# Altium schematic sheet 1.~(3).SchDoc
size 420 x 297 mm
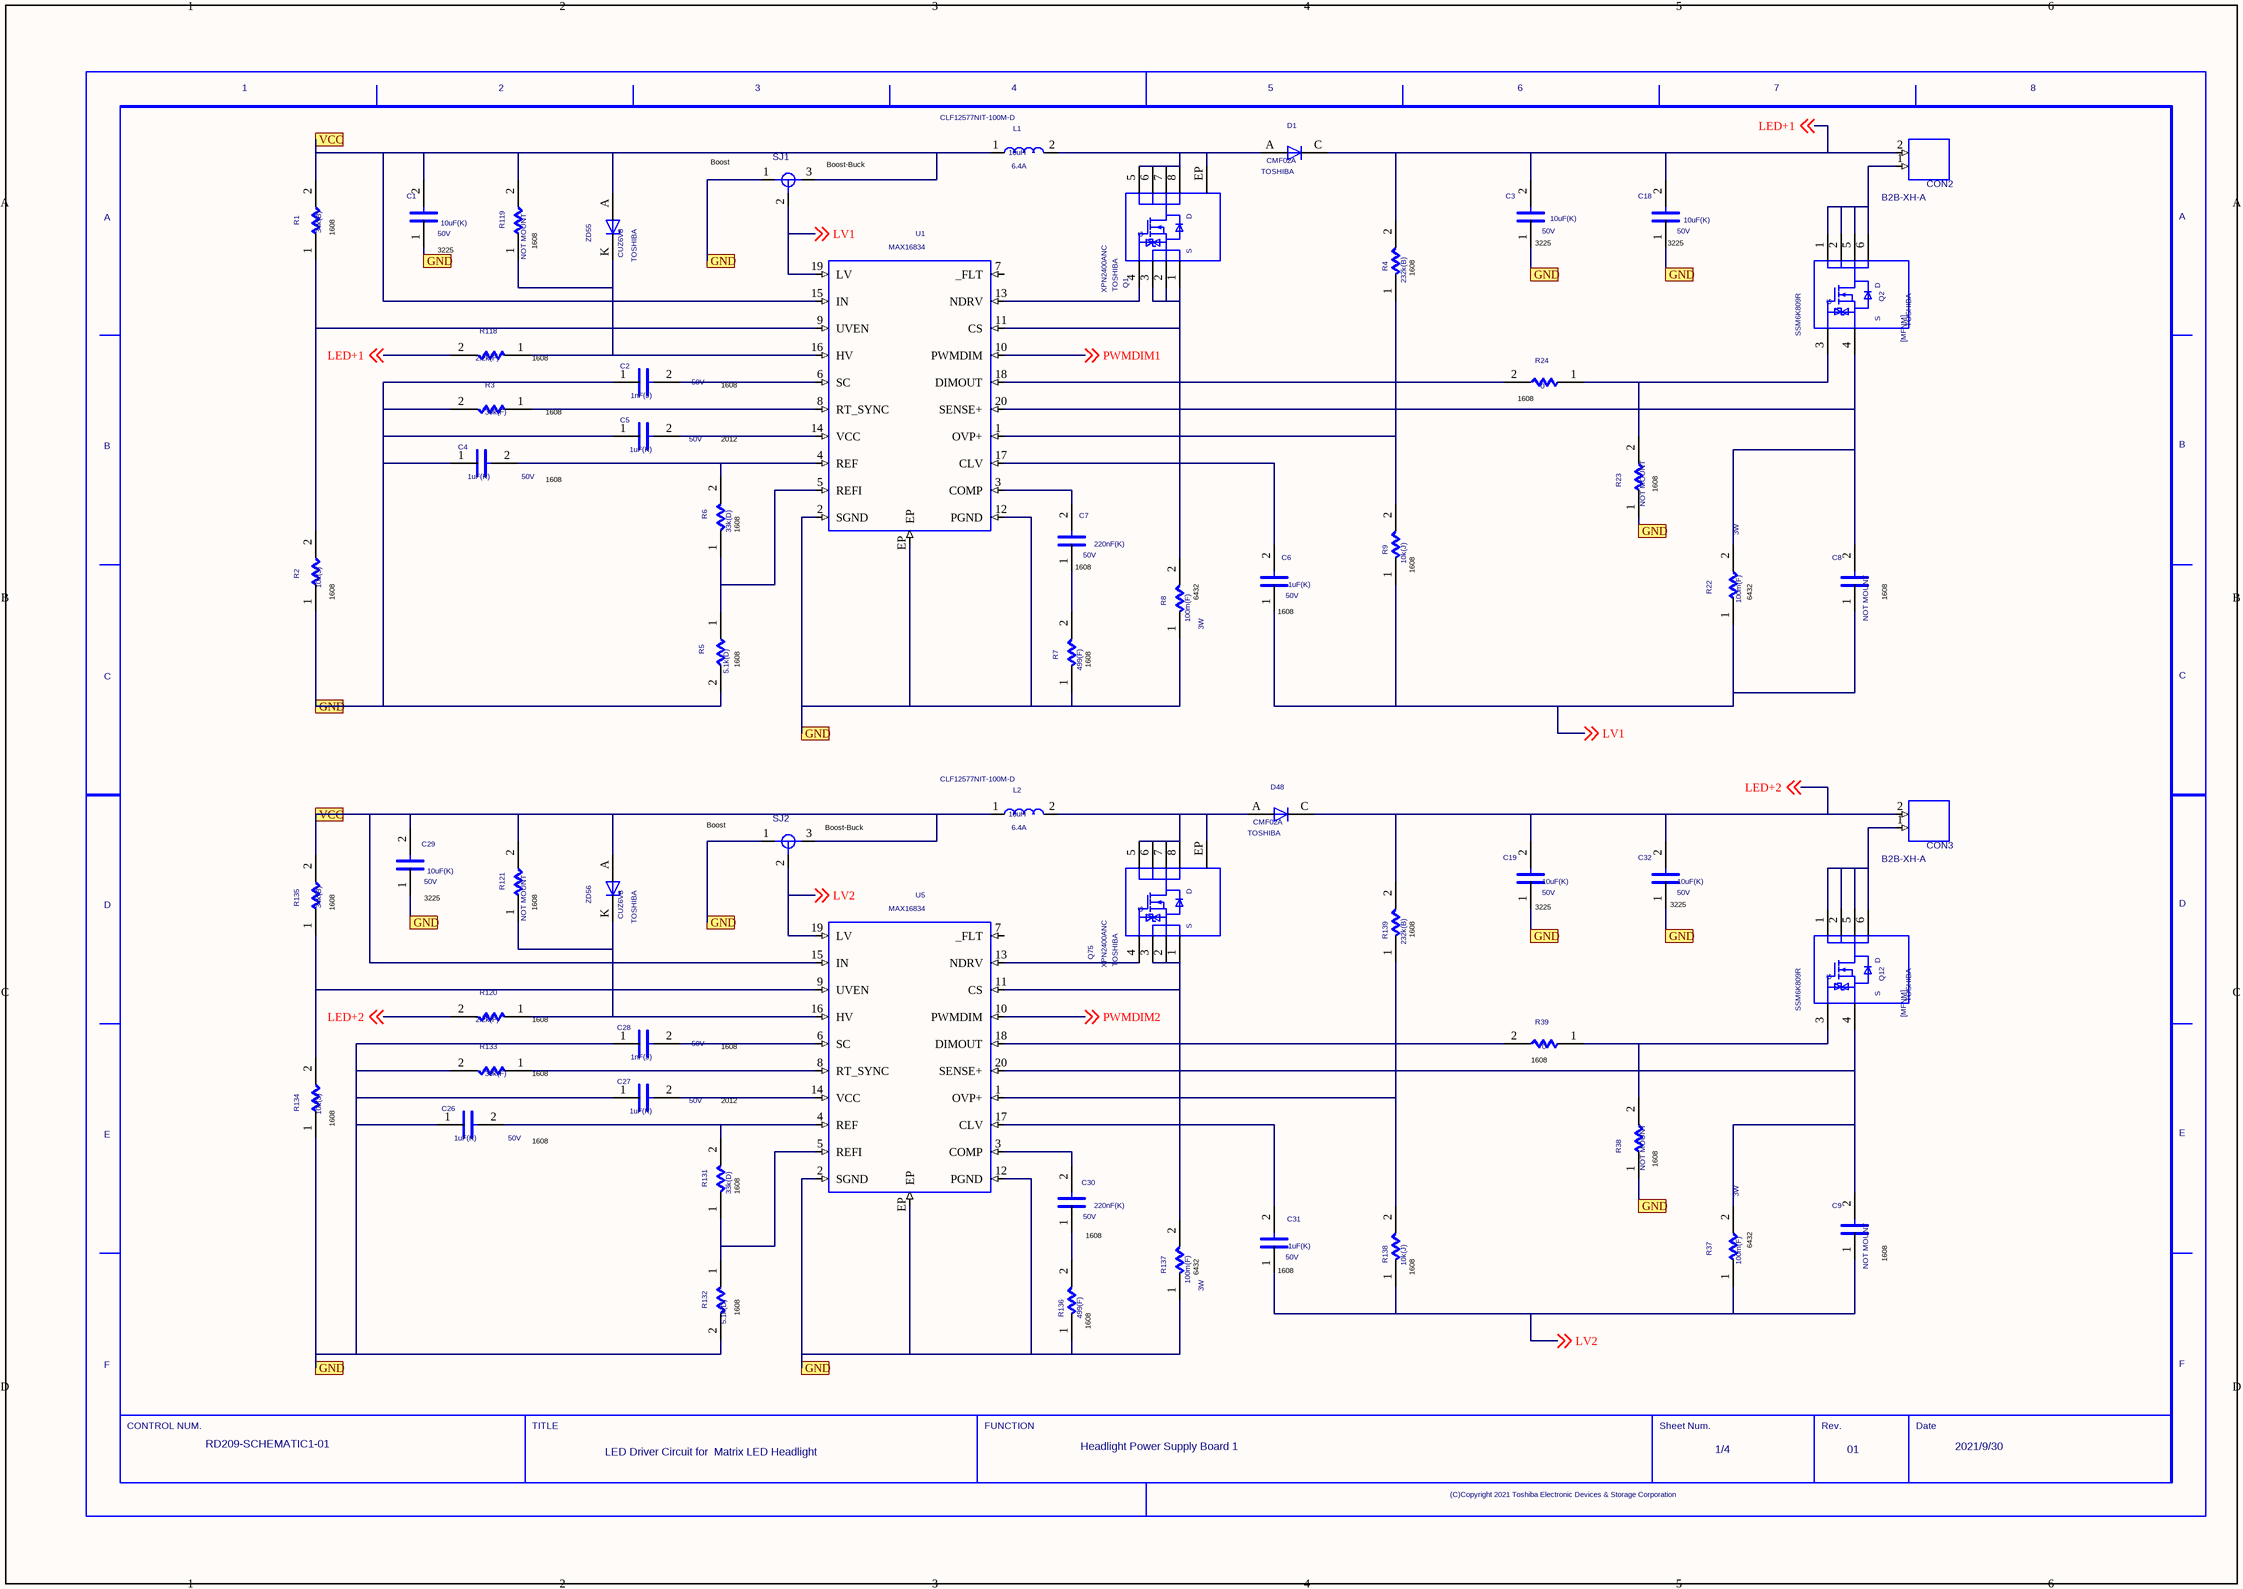
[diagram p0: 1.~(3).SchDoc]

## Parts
C1  VAL2: 50V  VAL1: 10uF(K)  (hidden comment: C)
C2  VAL2: 50V  VAL1: 1nF(J)  (hidden comment: C)
C3  VAL2: 50V  VAL1: 10uF(K)  (hidden comment: C)
C4  VAL2: 50V  VAL1: 1uF(K)  (hidden comment: C)
C5  VAL2: 50V  VAL1: 1uF(K)  (hidden comment: C)
C6  VAL2: 50V  VAL1: 1uF(K)  (hidden comment: C)
C7  VAL2: 50V  VAL1: 220nF(K)  (hidden comment: C)
C8  NOTMOUNT: NOT MOUNT  (hidden comment: C)
C9  NOTMOUNT: NOT MOUNT  (hidden comment: C)
C18  VAL2: 50V  VAL1: 10uF(K)  (hidden comment: C)
C19  VAL2: 50V  VAL1: 10uF(K)  (hidden comment: C)
C26  VAL2: 50V  VAL1: 1uF(K)  (hidden comment: C)
C27  VAL2: 50V  VAL1: 1uF(K)  (hidden comment: C)
C28  VAL2: 50V  VAL1: 1nF(J)  (hidden comment: C)
C29  VAL2: 50V  VAL1: 10uF(K)  (hidden comment: C)
C30  VAL2: 50V  VAL1: 220nF(K)  (hidden comment: C)
C31  VAL2: 50V  VAL1: 1uF(K)  (hidden comment: C)
C32  VAL2: 50V  VAL1: 10uF(K)  (hidden comment: C)
CON2  B2B-XH-A  [B2B-XH-A]
CON3  B2B-XH-A  [B2B-XH-A]
D1  USERCOMPTEXT3: TOSHIBA  VAL3: CMF02A  (hidden comment: D)
D48  USERCOMPTEXT3: TOSHIBA  VAL3: CMF02A  (hidden comment: D)
L1  VAL3: CLF12577NIT-100M-D  VAL2: 6.4A  VAL1: 10uH  (hidden comment: L)
L2  VAL3: CLF12577NIT-100M-D  VAL2: 6.4A  VAL1: 10uH  (hidden comment: L)
Q1  USERCOMPTEXT3: TOSHIBA  VAL3: XPN2400ANC  (hidden comment: MFNKR1)
Q2  USERCOMPTEXT3: TOSHIBA  VAL3: SSM6K809R  (hidden comment: MFNM)
Q12  USERCOMPTEXT3: TOSHIBA  VAL3: SSM6K809R  (hidden comment: MFNM)
Q75  USERCOMPTEXT3: TOSHIBA  VAL3: XPN2400ANC  (hidden comment: MFNKR1)
R1  VAL1: 34k(B)  (hidden comment: R)
R2  VAL1: 10k(J)  (hidden comment: R)
R3  VAL1: 39k(F)  (hidden comment: R)
R4  VAL1: 232k(B)  (hidden comment: R)
R5  VAL1: 5.1k(D)  (hidden comment: R)
R6  VAL1: 33k(D)  (hidden comment: R)
R7  VAL1: 499(F)  (hidden comment: R)
R8  VAL2: 3W  VAL1: 100m(F)  (hidden comment: R)
R9  VAL1: 10k(J)  (hidden comment: R)
R22  VAL2: 3W  VAL1: 100m(F)  (hidden comment: R)
R23  NOTMOUNT: NOT MOUNT  (hidden comment: R)
R24  VAL1: 0  (hidden comment: R)
R37  VAL2: 3W  VAL1: 100m(F)  (hidden comment: R)
R38  NOTMOUNT: NOT MOUNT  (hidden comment: R)
R39  VAL1: 0  (hidden comment: R)
R118  VAL1: 2.2k(F)  (hidden comment: R)
R119  NOTMOUNT: NOT MOUNT  (hidden comment: R)
R120  VAL1: 2.2k(F)  (hidden comment: R)
R121  NOTMOUNT: NOT MOUNT  (hidden comment: R)
R131  VAL1: 33k(D)  (hidden comment: R)
R132  VAL1: 5.1k(D)  (hidden comment: R)
R133  VAL1: 39k(F)  (hidden comment: R)
R134  VAL1: 10k(J)  (hidden comment: R)
R135  VAL1: 34k(B)  (hidden comment: R)
R136  VAL1: 499(F)  (hidden comment: R)
R137  VAL2: 3W  VAL1: 100m(F)  (hidden comment: R)
R138  VAL1: 10k(J)  (hidden comment: R)
R139  VAL1: 232k(B)  (hidden comment: R)
SJ1  SJ2W  (value not drawn)
SJ2  SJ2W  (value not drawn)
U1  MAX16834
U5  MAX16834
U?  DATE: 2021/9/30  REVISION: 01  SHEETNUMBER: 1/4  FUNCTION: Headlight Power Supply Board 1  TITLE: LED Driver Circuit for / Matrix LED Headlight  DRAWINGNUMBER: RD209-SCHEMATIC1-01  (hidden comment: WAKU_DEF100)
ZD55  USERCOMPTEXT3: TOSHIBA  VAL3: CUZ6V8  (hidden comment: ZD)
ZD56  USERCOMPTEXT3: TOSHIBA  VAL3: CUZ6V8  (hidden comment: ZD)

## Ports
GND, VCC

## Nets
GND: C1.1 C2.1 C3.1 C4.1 C5.1 C18.1 C19.1 C26.1 C27.1 C28.1 C29.1 C32.1 R2.1 R3.2 R5.2 R7.1 R8.1 R23.1 R38.1 R132.2 R133.2 R134.1 R136.1 R137.1 SJ1.1 SJ2.1 U1.2(SGND) U1.12(PGND) U1.EP U5.2(SGND) U5.12(PGND) U5.EP ; port GND
LED+1: C3.2 C18.2 CON2.2 D1.C R4.2 R118.2 ; off-sheet LED+1
LED+2: C19.2 C32.2 CON3.2 D48.C R120.2 R139.2 ; off-sheet LED+2
LED-1: CON2.1 Q2.1 Q2.2 Q2.5 Q2.6
LV1: C6.1 C8.1 R9.1 R22.1 SJ1.2 U1.19(LV) ; off-sheet LV1
LV2: C9.1 C31.1 R37.1 R138.1 SJ2.2 U5.19(LV) ; off-sheet LV2
N00268: R5.1 R6.1 U1.5(REFI)
N00273: R3.1 U1.8(RT_SYNC)
N00275: R1.1 R2.2 U1.9(UVEN)
N00392: D1.A L1.2 Q1.5 Q1.6 Q1.7 Q1.8 Q1.EP
N00398: C7.2 U1.3(COMP)
N00400: C6.2 U1.17(CLV)
N00402: R4.1 R9.2 U1.1(OVP+)
N00897: C8.2 Q2.4 R22.2 U1.20(SENSE+)
N00907: R24.2 U1.18(DIMOUT)
N00925: R118.1 R119.1 U1.16(HV) ZD55.K(C)
N01084: C4.2 R6.2 U1.4(REF)
PWMDIM1: U1.10(PWMDIM) ; off-sheet PWMDIM1
PWMDIM2: U5.10(PWMDIM) ; off-sheet PWMDIM2
SIG2: Q1.1 Q1.2 Q1.3 R8.2 U1.11(CS)
SIG212: C5.2 U1.14(VCC)
SIG213: C2.2 U1.6(SC)
SIG216: Q1.4 U1.13(NDRV)
SIG218: C7.1 R7.2
SIG223: Q2.3 R23.2 R24.1
SIG224: R133.1 U5.8(RT_SYNC)
SIG225: C28.2 U5.6(SC)
SIG229: C26.2 R131.2 U5.4(REF)
SIG230: C31.2 U5.17(CLV)
SIG231: C27.2 U5.14(VCC)
SIG233: R134.2 R135.1 U5.9(UVEN)
SIG235: C30.2 U5.3(COMP)
SIG236: Q75.1 Q75.2 Q75.3 R137.2 U5.11(CS)
SIG237: R138.2 R139.1 U5.1(OVP+)
SIG238: R120.1 R121.1 U5.16(HV) ZD56.K(C)
SIG243: C30.1 R136.2
SIG244: Q12.3 R38.2 R39.1
SIG245: R131.1 R132.1 U5.5(REFI)
SIG250: D48.A L2.2 Q75.5 Q75.6 Q75.7 Q75.8 Q75.EP
SIG251: Q75.4 U5.13(NDRV)
SIG662: R39.2 U5.18(DIMOUT)
SIG663: CON3.1 Q12.1 Q12.2 Q12.5 Q12.6
SIG664: C9.2 Q12.4 R37.2 U5.20(SENSE+)
VCC: C1.2 C29.2 L1.1 L2.1 R1.2 R119.2 R121.2 R135.2 SJ1.3 SJ2.3 U1.15(IN) U5.15(IN) ZD55.A ZD56.A ; port VCC

Not connected (* = marked no-connect by the designer): U1 7(_FLT); U5 7(_FLT)

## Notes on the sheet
- (near SJ1) Boost
- (near SJ1) Boost-Buck
- (near R1) 1608
- (near C1) 3225
- (near R119) 1608
- (near C3) 3225
- (near C18) 3225
- (near R4) 1608
- (near R118) 1608
- 1608
- (near R3) 1608
- 2012
- (near R24) 1608
- (near R6) 1608
- (near R23) 1608
- (near R2) 1608
- (near C7) 1608
- (near R8) 6432
- (near R9) 1608
- (near R22) 6432
- (near C8) 1608
- (near R5) 1608
- (near R7) 1608
- (near C6) 1608
- (near SJ2) Boost
- (near SJ2) Boost-Buck
- (near R135) 1608
- (near C29) 3225
- (near R121) 1608
- (near R139) 1608
- (near C19) 3225
- (near C32) 3225
- (near R120) 1608
- (near R39) 1608
- (near R134) 1608
- (near R133) 1608
- (near R131) 1608
- (near R38) 1608
- (near R137) 6432
- (near C31) 1608
- (near R138) 1608
- (near R37) 6432
- (near C9) 1608
- (near R132) 1608
- (near R136) 1608

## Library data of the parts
C1 = C: TIME: 17:22:43; UPDATEUSER: t5459927; SAVECOUNT: 1; OriginalSymbolOrigin: (2540,7620); INSTANCENAME: cmp468; CDBNAME: C1210K
C2 = C: TIME: 17:22:43; UPDATEUSER: t5459927; SAVECOUNT: 1; OriginalSymbolOrigin: (2540,7620); INSTANCENAME: cmp462; CDBNAME: C0603K_1
C3 = C: TIME: 17:22:43; UPDATEUSER: t5459927; SAVECOUNT: 1; OriginalSymbolOrigin: (2540,7620); INSTANCENAME: cmp474; CDBNAME: C1210K
C4 = C: TIME: 17:22:43; UPDATEUSER: t5459927; SAVECOUNT: 1; OriginalSymbolOrigin: (2540,7620); INSTANCENAME: cmp457; CDBNAME: C0603K_3
C5 = C: TIME: 17:22:43; UPDATEUSER: t5459927; SAVECOUNT: 1; OriginalSymbolOrigin: (2540,7620); INSTANCENAME: cmp459; CDBNAME: C0805K_1
C6 = C: TIME: 17:22:43; UPDATEUSER: t5459927; SAVECOUNT: 1; OriginalSymbolOrigin: (2540,7620); INSTANCENAME: cmp481; CDBNAME: C0603K_3
C7 = C: TIME: 17:22:43; UPDATEUSER: t5459927; SAVECOUNT: 1; OriginalSymbolOrigin: (2540,7620); INSTANCENAME: cmp482; CDBNAME: C0603K_4
C8 = C: TIME: 17:22:43; UPDATEUSER: t5459927; SAVECOUNT: 1; OriginalSymbolOrigin: (2540,7620); INSTANCENAME: cmp493; CDBNAME: C0603K
C9 = C: TIME: 17:22:43; UPDATEUSER: t5459927; SAVECOUNT: 1; OriginalSymbolOrigin: (2540,7620); INSTANCENAME: cmp590; CDBNAME: C0603K
C18 = C: TIME: 17:22:43; UPDATEUSER: t5459927; SAVECOUNT: 1; OriginalSymbolOrigin: (2540,7620); INSTANCENAME: cmp472; CDBNAME: C1210K
C19 = C: TIME: 17:22:43; UPDATEUSER: t5459927; SAVECOUNT: 1; OriginalSymbolOrigin: (2540,7620); INSTANCENAME: cmp593; CDBNAME: C1210K
C26 = C: TIME: 17:22:43; UPDATEUSER: t5459927; SAVECOUNT: 1; OriginalSymbolOrigin: (2540,7620); INSTANCENAME: cmp560; CDBNAME: C0603K_3
C27 = C: TIME: 17:22:43; UPDATEUSER: t5459927; SAVECOUNT: 1; OriginalSymbolOrigin: (2540,7620); INSTANCENAME: cmp586; CDBNAME: C0805K_1
C28 = C: TIME: 17:22:43; UPDATEUSER: t5459927; SAVECOUNT: 1; OriginalSymbolOrigin: (2540,7620); INSTANCENAME: cmp596; CDBNAME: C0603K_1
C29 = C: TIME: 17:22:43; UPDATEUSER: t5459927; SAVECOUNT: 1; OriginalSymbolOrigin: (2540,7620); INSTANCENAME: cmp558; CDBNAME: C1210K
C30 = C: TIME: 17:22:43; UPDATEUSER: t5459927; SAVECOUNT: 1; OriginalSymbolOrigin: (2540,7620); INSTANCENAME: cmp562; CDBNAME: C0603K_4
C31 = C: TIME: 17:22:43; UPDATEUSER: t5459927; SAVECOUNT: 1; OriginalSymbolOrigin: (2540,7620); INSTANCENAME: cmp584; CDBNAME: C0603K_3
C32 = C: TIME: 17:22:43; UPDATEUSER: t5459927; SAVECOUNT: 1; OriginalSymbolOrigin: (2540,7620); INSTANCENAME: cmp554; CDBNAME: C1210K
CON2 CON3 = B2B_XH_A: SAVECOUNT: 1; COMP: B2_BX_HA; UPDATEUSER: t5459927; UPDATETIME: 17:22:42; OriginalSymbolOrigin: (0,0); COMPONENTNAME: CON; INSTANCENAME: INS9160
D1 D48 = D: SAVEAREA0: -225,-91,12804,7836; SAVECOUNT: 3; TIME: 14:49:55; UPDATEUSER: 19870035; UPDATETIME: 14:20:16; OriginalSymbolOrigin: (5080,5080); CDBNAME: M-FLAT
L1 = L: COMP: CLF12577NI_D; TIME: 17:22:43; UPDATEUSER: t5459927; SAVECOUNT: 1; OriginalSymbolOrigin: (2540,5080); INSTANCENAME: cmp470; CDBNAME: CLF12577NI-D
L2 = L: COMP: CLF12577NI_D; TIME: 17:22:43; UPDATEUSER: t5459927; SAVECOUNT: 1; OriginalSymbolOrigin: (2540,5080); INSTANCENAME: cmp575; CDBNAME: CLF12577NI-D
Q1 Q75 = MFNKR1: TIME: 17:22:43; SAVECOUNT: 2; SAVEAREA0: -5755,-491,27794,24105; COMP: TSON_ADVANCE_WF_1; UPDATETIME: 09:26:31; UPDATEUSER: t5459927; OriginalSymbolOrigin: (5080,20320); COMPONENTNAME: Q
Q2 = MFNM: TIME: 17:22:43; SAVECOUNT: 1; SAVEAREA0: -6986,-322,29385,23602; UPDATEUSER: t5459927; OriginalSymbolOrigin: (5080,20320); COMPONENTNAME: Q; INSTANCENAME: cmp496; CDBNAME: TSOP6F
Q12 = MFNM: TIME: 17:22:43; SAVECOUNT: 1; SAVEAREA0: -6986,-322,29385,23602; UPDATEUSER: t5459927; OriginalSymbolOrigin: (5080,20320); COMPONENTNAME: Q; INSTANCENAME: cmp553; CDBNAME: TSOP6F
R1 = R: TIME: 17:22:43; UPDATEUSER: t5459927; SAVECOUNT: 1; OriginalSymbolOrigin: (5080,5080); VAL2: 100mW; INSTANCENAME: cmp447; CDBNAME: R0603_1
R2 = R: TIME: 17:22:43; UPDATEUSER: t5459927; SAVECOUNT: 1; OriginalSymbolOrigin: (5080,5080); VAL2: 100mW; INSTANCENAME: cmp448; CDBNAME: R0603_6
R3 = R: TIME: 17:22:43; UPDATEUSER: t5459927; SAVECOUNT: 1; OriginalSymbolOrigin: (5080,5080); VAL2: 100mW; INSTANCENAME: cmp460; CDBNAME: R0603_8
R4 = R: TIME: 17:22:43; UPDATEUSER: t5459927; SAVECOUNT: 1; OriginalSymbolOrigin: (5080,5080); VAL2: 63mW; INSTANCENAME: cmp478; CDBNAME: R0603_9
R5 = R: TIME: 17:22:43; UPDATEUSER: t5459927; SAVECOUNT: 1; OriginalSymbolOrigin: (5080,5080); VAL2: 100mW; INSTANCENAME: cmp450; CDBNAME: R0603_10
R6 = R#1: TIME: 17:22:43; UPDATEUSER: t5459927; SAVECOUNT: 1; OriginalSymbolOrigin: (5080,5080); CaptureCellPackProp: R##1; VAL2: 100mW; INSTANCENAME: cmp606; CDBNAME: R0603_11
R7 = R: TIME: 17:22:43; UPDATEUSER: t5459927; SAVECOUNT: 1; OriginalSymbolOrigin: (5080,5080); VAL2: 125mW; INSTANCENAME: cmp483; CDBNAME: R0603_12
R8 = R: TIME: 17:22:43; UPDATEUSER: t5459927; SAVECOUNT: 1; OriginalSymbolOrigin: (5080,5080); INSTANCENAME: cmp484; CDBNAME: R2512
R9 = R: TIME: 17:22:43; UPDATEUSER: t5459927; SAVECOUNT: 1; OriginalSymbolOrigin: (5080,5080); VAL2: 100mW; INSTANCENAME: cmp479; CDBNAME: R0603_6
R22 = R: TIME: 17:22:43; UPDATEUSER: t5459927; SAVECOUNT: 1; OriginalSymbolOrigin: (5080,5080); INSTANCENAME: cmp492; CDBNAME: R2512
R23 = R: TIME: 17:22:43; UPDATEUSER: t5459927; SAVECOUNT: 1; OriginalSymbolOrigin: (5080,5080); INSTANCENAME: cmp489; CDBNAME: R0603
R24 = R: TIME: 17:22:43; UPDATEUSER: t5459927; SAVECOUNT: 1; OriginalSymbolOrigin: (5080,5080); INSTANCENAME: cmp498; CDBNAME: R0603_7
R37 = R: TIME: 17:22:43; UPDATEUSER: t5459927; SAVECOUNT: 1; OriginalSymbolOrigin: (5080,5080); INSTANCENAME: cmp559; CDBNAME: R2512
R38 = R: TIME: 17:22:43; UPDATEUSER: t5459927; SAVECOUNT: 1; OriginalSymbolOrigin: (5080,5080); INSTANCENAME: cmp592; CDBNAME: R0603
R39 = R: TIME: 17:22:43; UPDATEUSER: t5459927; SAVECOUNT: 1; OriginalSymbolOrigin: (5080,5080); INSTANCENAME: cmp550; CDBNAME: R0603_7
R118 = R: TIME: 17:22:43; UPDATEUSER: t5459927; SAVECOUNT: 1; OriginalSymbolOrigin: (5080,5080); VAL2: 100mW; INSTANCENAME: cmp466; CDBNAME: R0603_2
R119 = R: TIME: 17:22:43; UPDATEUSER: t5459927; SAVECOUNT: 1; OriginalSymbolOrigin: (5080,5080); INSTANCENAME: cmp469; CDBNAME: R0603
R120 = R: TIME: 17:22:43; UPDATEUSER: t5459927; SAVECOUNT: 1; OriginalSymbolOrigin: (5080,5080); VAL2: 100mW; INSTANCENAME: cmp591; CDBNAME: R0603_2
R121 = R: TIME: 17:22:43; UPDATEUSER: t5459927; SAVECOUNT: 1; OriginalSymbolOrigin: (5080,5080); INSTANCENAME: cmp582; CDBNAME: R0603
R131 = R#1: TIME: 17:22:43; UPDATEUSER: t5459927; SAVECOUNT: 1; OriginalSymbolOrigin: (5080,5080); CaptureCellPackProp: R##1; VAL2: 100mW; INSTANCENAME: cmp607; CDBNAME: R0603_11
R132 = R: TIME: 17:22:43; UPDATEUSER: t5459927; SAVECOUNT: 1; OriginalSymbolOrigin: (5080,5080); VAL2: 100mW; INSTANCENAME: cmp551; CDBNAME: R0603_10
R133 = R: TIME: 17:22:43; UPDATEUSER: t5459927; SAVECOUNT: 1; OriginalSymbolOrigin: (5080,5080); VAL2: 100mW; INSTANCENAME: cmp579; CDBNAME: R0603_8
R134 = R: TIME: 17:22:43; UPDATEUSER: t5459927; SAVECOUNT: 1; OriginalSymbolOrigin: (5080,5080); VAL2: 100mW; INSTANCENAME: cmp595; CDBNAME: R0603_6
R135 = R: TIME: 17:22:43; UPDATEUSER: t5459927; SAVECOUNT: 1; OriginalSymbolOrigin: (5080,5080); VAL2: 100mW; INSTANCENAME: cmp561; CDBNAME: R0603_1
R136 = R: TIME: 17:22:43; UPDATEUSER: t5459927; SAVECOUNT: 1; OriginalSymbolOrigin: (5080,5080); VAL2: 125mW; INSTANCENAME: cmp555; CDBNAME: R0603_12
R137 = R: TIME: 17:22:43; UPDATEUSER: t5459927; SAVECOUNT: 1; OriginalSymbolOrigin: (5080,5080); INSTANCENAME: cmp571; CDBNAME: R2512
R138 = R: TIME: 17:22:43; UPDATEUSER: t5459927; SAVECOUNT: 1; OriginalSymbolOrigin: (5080,5080); VAL2: 100mW; INSTANCENAME: cmp564; CDBNAME: R0603_6
R139 = R: TIME: 17:22:43; UPDATEUSER: t5459927; SAVECOUNT: 1; OriginalSymbolOrigin: (5080,5080); VAL2: 63mW; INSTANCENAME: cmp581; CDBNAME: R0603_9
SJ1 = SJ2W: SAVECOUNT: 1; COMP: SJ_2; SAVEAREA0: -15743,-4510,23437,11881; UPDATEUSER: t5459927; UPDATETIME: 17:22:42; OriginalSymbolOrigin: (2540,7620); COMPONENTNAME: SJ; INSTANCENAME: cmp600
SJ2 = SJ2W: SAVECOUNT: 1; COMP: SJ_2; SAVEAREA0: -15743,-4510,23437,11881; UPDATEUSER: t5459927; UPDATETIME: 17:22:42; OriginalSymbolOrigin: (2540,7620); COMPONENTNAME: SJ; INSTANCENAME: cmp604
U1 U5 = MAX16834: SAVECOUNT: 1; COMP: 20-TQFN; SAVEAREA0: -47937,-54417,76568,2975; UPDATEUSER: t5459927; UPDATETIME: 17:22:42; OriginalSymbolOrigin: (0,0); COMPONENTNAME: IC; INSTANCENAME: cmp580
U? = WAKU_DEF100: PLOTTIME: HH:MM; SAVEAREA0: 147884,-66467,487065,89883; TIME: 14:30:25; UPDATEUSER: t5459927; UPDATETIME: 12:50:54; SAVECOUNT: 7; OriginalSymbolOrigin: (10160,284480)
ZD55 = ZD: TIME: 17:22:43; SAVECOUNT: 1; SAVEAREA0: -4630,-153,17114,13055; UPDATEUSER: t5459927; OriginalSymbolOrigin: (5080,5080); INSTANCENAME: cmp445; CDBNAME: USC
ZD56 = ZD: TIME: 17:22:43; SAVECOUNT: 1; SAVEAREA0: -4630,-153,17114,13055; UPDATEUSER: t5459927; OriginalSymbolOrigin: (5080,5080); INSTANCENAME: cmp588; CDBNAME: USC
